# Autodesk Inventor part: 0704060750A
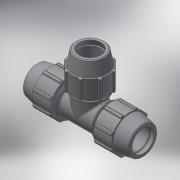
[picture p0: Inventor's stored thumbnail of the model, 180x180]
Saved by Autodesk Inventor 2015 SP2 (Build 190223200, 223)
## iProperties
Created: 2017-02
Part Number: 0704060750A
Material: Generic
Description: PLASSON TEE 75-75-75
Document SubType Name: Modeling
Designer: KIM
Mass: 2642.84 g
Surface Area: 3396.39 cm^2
Volume: 2642.84 cm^3
Density: 1 g/cm^3
Appearance: Default
Author: KIM
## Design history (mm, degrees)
derived "87040.ipt"
feature "Solid1::87040.ipt"
tag "TaggingFeature1"
body "Solid1"
other parameters: "d2" = 75, "d4" = 14.75, "d5" = 44.25, "d7" = 132, "d13" = 120 deg, "d14" = 97.5, "d15" = 12 deg, "d18" = 3.75, "d19" = 35 deg, "d20" = 17.5 deg, "d21" = 122.76, "d23" = 0, "d25" = 360 deg, "d27" = 2.64, "d42" = 61.95, "d43" = 3.96, "d46" = 2.25, "d63" = 132, "d67" = 99, "d76" = 75, "d77" = 132, "d78" = 12 deg, "d79" = 177, "d80" = 120 deg, "d81" = 97.5, "d82" = 14.75, "d85" = 99, "d87" = 5.9, "d88" = 5.9, "d89" = 44.25, "d90" = 61.95, "d98" = 122.76, "d99" = 35 deg, "d100" = 17.5 deg, "d102" = 0, "d103" = 2.64, "d107" = 360 deg, "d109" = 2.25, "d112" = 3.75, "d118" = 360 deg, "d121" = 0, "d128" = 353, "d131" = 67.5, "d132" = 67.5, "d133" = 132, "d134" = 2.64, "d152" = 0, "d154" = 0, "d156" = 0, "d158" = 0, "d163" = 12.9, "d165" = 14.22, "d166" = 94.05, "d167" = 94.05, "d168" = 4.74, "d169" = 108.9, "d170" = 2.37, "d171" = 3.555, "d172" = 108.9, "d173" = 4.3, "d174" = 2.15, "d175" = 3.225, "d176" = 1.5, "d177" = 3.75, "d_" = 75, "E_" = 132, "A_" = 177, "l_" = 132, "H_" = 353, "d162" = 25.8, "d164" = 28.44
